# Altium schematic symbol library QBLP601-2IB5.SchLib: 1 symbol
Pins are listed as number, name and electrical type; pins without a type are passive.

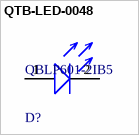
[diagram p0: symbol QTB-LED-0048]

## QTB-LED-0048
designator D?, comment QBLP601-2IB5
LED BLUE CLEAR 0603 SMD; Manufacturer: QT Brightek (QTB); Lens Size: 0.8mm; Luminous Intensity: 35mcd; Test Current: 5mA; Lens Color: Colorless; Lens Style: Flat; Forward Voltage: 2.7V; Wavelength - Dominant: 465nm
footprint QBLP601-2IB5-MFG
pins: 1 ANODE (+), 2 CATHODE (-)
